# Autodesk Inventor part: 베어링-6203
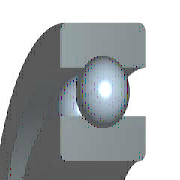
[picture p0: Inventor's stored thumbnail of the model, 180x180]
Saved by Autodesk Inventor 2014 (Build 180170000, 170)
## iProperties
IsCustomPart: 0
Created: 2016-05
Part Number: 베어링-6203
Material: 강철, 연강
Description: 깊은 그루브 볼 베어링
Document SubType Name: Modeling
Standard: KS B 2023
Designer: mduedu
Standards Organization: KS
Language: ko-KR
Size Designation: 6203 - 17 x 40 x 12
Categories: <MemberInstance><Categories><Category DisplayName="샤프트 부품" InternalName="7f7aeb1f-a693-4053-b835-cee3144e0d98" Mnemonic="SHFT"><Category DisplayName="베어링" Inter
Density: 1 g/cm^3
Appearance: 노란색
Author: mduedu
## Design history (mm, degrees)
sketch "스케치" dims "d0" = 5.98 (= -0.26 x WD + 0.26 x BD)
  geometry: L1 (3.01, 14.25)-(8.99, 14.25); L2 (6, 14.25)-(6, 11.26); L3 (6, 14.25)-(6, 17.24); L4 (3.778, 12.249)-(0, 12.249); L5 (0, 8.5)-(12, 8.5); L6 (3.778, 16.251)-(0, 16.251); L7 (0, 20)-(12, 20); L8 (12, 8.5)-(12, 12.249); L9 (8.222, 12.249)-(12, 12.249); L10 (8.222, 16.251)-(12, 16.251); L11 (12, 20)-(12, 16.251); L12 (-1.4, 0)-(8.4, 0) reference; L13 (0, -0.3)-(0, 5.3) reference
  constraints: 22 end point, 4 point on line, 2 collinear, 2 perpendicular, 2 symmetric about line, 1 midpoint, 1 parallel, 14 other
  dimensions: "d9" = 17 diameter of L5 L12 (= WD); "d11" = 40 diameter of L7 L12 (= BD); "d12" = 12 distance between parallel lines of L8 L13 (= KB); "d13" = 24.498 diameter of L9 L12 (= 0.326 x BD + 0.674 x WD)
revolve "본체" stored, may be unused: angle "d6" = 90 deg
revolve "볼" stored, may be unused: angle "d7" = 90 deg
pattern_circular "IDS_ARRAYBALL[SIMPL:T]" dims angle "d3" = 360 deg
body "Solid1"
fillet "모깎기1" dims "d1" = 0.6 (= KRS)
other parameters: "WD" = 17 [user parameter; used in 5 equation terms], "BD" = 40 [user parameter; used in 5 equation terms], "KB" = 12 [user parameter; used in 1 equation term], "KRS" = 0.6 [user parameter; used in 1 equation term], "d4" = 0, "d5" = 0, "d8" = 0, "d14" = 0, "d15" = 0, "BBA" = 0 [user parameter], "BC0" = 4750000 [user parameter], "BC" = 9560000 [user parameter], "WR" = 8.5 (= 0.5 x WD) [user parameter]
